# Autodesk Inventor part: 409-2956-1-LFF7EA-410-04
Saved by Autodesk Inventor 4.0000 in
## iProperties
Created: 2010-06
Part Number: 409-2956-1-LFF7EA-410-04
Cost Center: 0 lbmass
Material: A304 STAINLESS STEEL
Document SubType Name: Sheet Metal
Designer: S. Boerckel
Authority: 0 in^3
Mass: 155.751 g
Surface Area: 164.242 cm^2
Volume: 19.2761 cm^3
Density: 8.08 g/cm^3
Flat Pattern Width: 10.16 cm
Flat Pattern Length: 10.16 cm
Flat Pattern Area: 103.226 cm^2
Sheet Metal Rule: 12Ga
Sheet Metal Width: 4.0000 in
Sheet Metal Length: 16.0000 in^2
Description: STRAINER 186Ga SHIM
User Status: BURN
SaveDate: 2008-01-15
SaveTime: 10:24
FileName: Sheet Metal
Wide: =<Flat Pattern Width>cm
Length: =<Flat Pattern Length>cm
Thickness: 0.1046 in
SMR: =<Sheet Metal Rule> - <Material>
Author: S. Boerckel
Revision Number: 0
Title: STRAINER 18Ga SHIM
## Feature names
1. Plate1
2. Cut1
